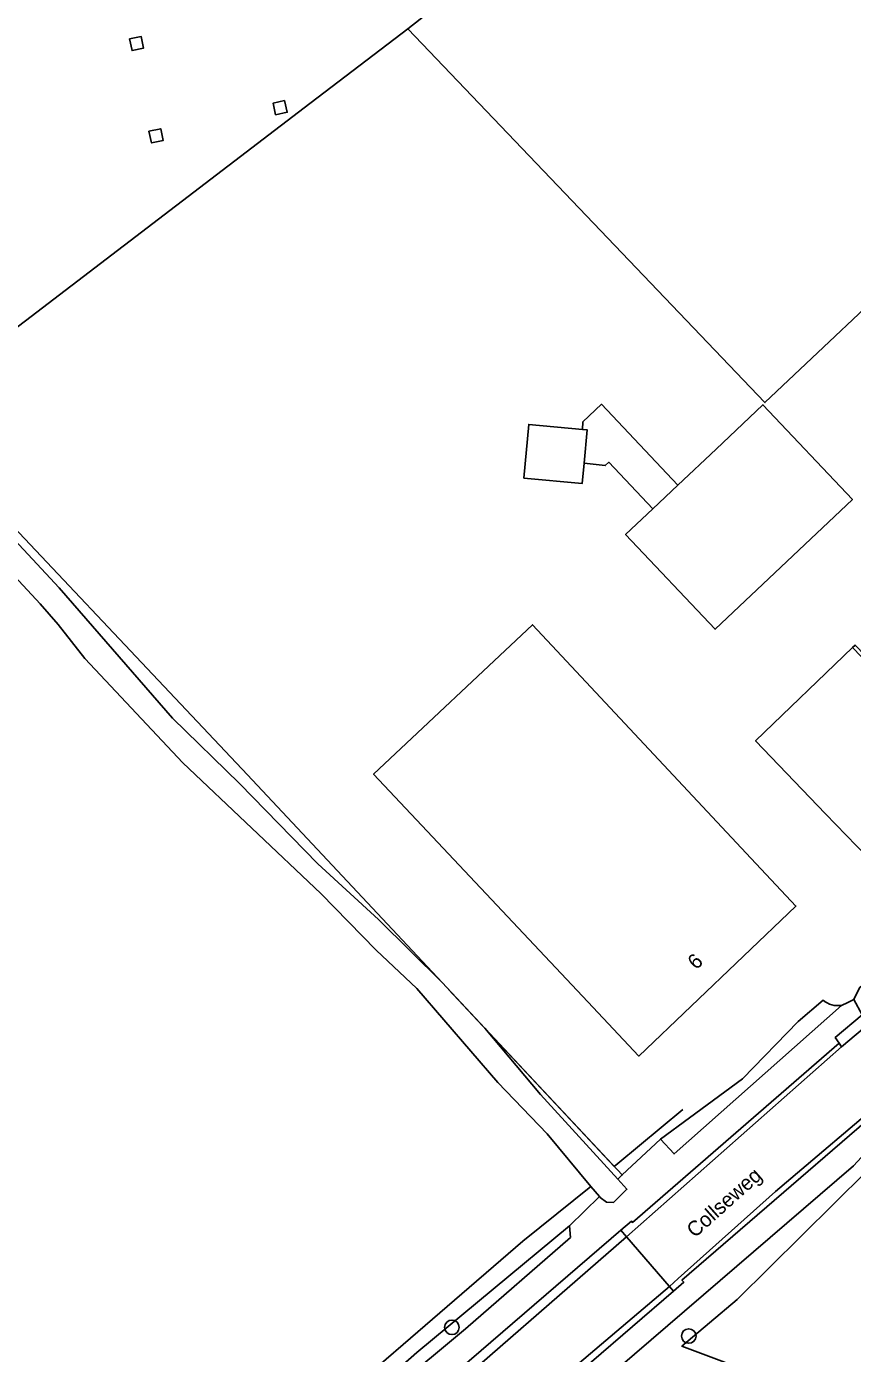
# Model space of a CAD drawing. Extents: x 164494 to 166241, y 382475 to 384495.
# Drawn here: x 165298.9 to 165354.5, y 384025.1 to 384114.4 of the extents above; entities that cross this region are included whole.
import ezdxf

# ---------------------------------------------------------------- set-up
doc = ezdxf.new("R2010")
doc.units = 0
for name, color, linetype in [('IMGEO_Berm_halfverhard', 7, 'Continuous'), ('IMGEO_Berm_open', 7, 'Continuous'), ('IMGEO_Boom', 7, 'Continuous'), ('IMGEO_Erf', 7, 'Continuous'), ('IMGEO_Grasland_agrarisch', 7, 'Continuous'), ('IMGEO_Grasland_overig', 7, 'Continuous'), ('IMGEO_Groenvoorziening', 7, 'Continuous'), ('IMGEO_Hek', 7, 'Continuous'), ('IMGEO_Hoogspanningsmast', 7, 'Continuous'), ('IMGEO_Openbare_ruimte_label', 7, 'Continuous'), ('IMGEO_Pand', 7, 'Continuous'), ('IMGEO_Pand_nummerreeks', 7, 'Continuous'), ('IMGEO_Rijbaan_lokaal_gesloten', 7, 'Continuous'), ('IMGEO_Waterloop', 7, 'Continuous')]:
    doc.layers.add(name, color=color, linetype=linetype)

msp = doc.modelspace()

# ---------------------------------------------------------------- linework, layer by layer
at = {"layer": 'IMGEO_Berm_halfverhard'}
msp.add_lwpolyline([(165398.089, 384073.33), (165398.624, 384073.651), (165398.403, 384074.002), (165394.851, 384071.884), (165389.473, 384068.311), (165384.606, 384064.9), (165379.087, 384060.555), (165368.742, 384052.317), (165357.153, 384042.664), (165349.337, 384036.022), (165342.774, 384030.162), (165342.196, 384029.629), (165342.457, 384029.327), (165343.149, 384029.924), (165343.032, 384030.052), (165361.191, 384045.73)], dxfattribs=at)
for points in [[(165353.778, 384045.772), (165353.618, 384046.006), (165339.695, 384033.942), (165339.626, 384034.037), (165338.914, 384033.424), (165339.3, 384032.977)], [(165339.3, 384032.977), (165338.914, 384033.424), (165325.135, 384021.562), (165325.577, 384021.044)], [(165342.457, 384029.327), (165342.196, 384029.629), (165342.192, 384029.633), (165328.3, 384017.851), (165328.304, 384017.847), (165328.664, 384017.425)]]:
    msp.add_lwpolyline(points, close=True, dxfattribs=at)
at = {"layer": 'IMGEO_Berm_open'}
msp.add_lwpolyline([(165380.141, 384067.277), (165379.794, 384067.601), (165367.867, 384058.185), (165366.467, 384057.026), (165355.319, 384047.804), (165355.158, 384047.926), (165353.349, 384046.386), (165353.618, 384046.006), (165353.778, 384045.772), (165361.803, 384052.529)], close=True, dxfattribs=at)
at = {"layer": 'IMGEO_Boom'}
for centre in [(165327.543, 384026.884), (165343.493, 384026.298)]:
    msp.add_circle(centre, 0.489, dxfattribs=at)
at = {"layer": 'IMGEO_Erf'}
for points in [[(165391.678, 384085.733), (165388.411, 384089.95), (165382.449, 384096.307), (165369.932, 384109.251), (165348.615, 384089.13), (165324.577, 384114.294), (165317.6, 384108.966), (165252.153, 384058.979), (165253.127, 384057.056), (165268.295, 384067.905), (165290.735, 384085.47), (165292.37, 384086.749), (165313.785, 384064.085), (165326.891, 384050.086), (165329.75, 384047.033), (165339.009, 384037.144), (165341.59, 384039.543), (165343.541, 384040.983), (165347.115, 384043.622), (165350.846, 384047.468), (165352.53, 384048.91)], [(165353.783, 384048.557), (165354.194, 384048.759), (165354.605, 384048.96), (165354.993, 384049.748), (165365.174, 384058.493), (165365.22, 384058.534), (165379.994, 384071.652)]]:
    msp.add_lwpolyline(points, dxfattribs=at)
for points in [[(165354.508, 384082.604), (165345.259, 384073.877), (165339.236, 384080.26), (165341.068, 384081.988), (165338.113, 384085.12), (165337.868, 384084.889), (165336.438, 384085.049), (165336.314, 384083.697), (165332.389, 384084.057), (165332.72, 384087.663), (165336.344, 384087.331), (165336.359, 384087.849), (165337.606, 384089.026), (165342.75, 384083.575), (165345.33, 384086.01), (165348.485, 384088.987)], [(165370.222, 384071.391), (165367.373, 384068.646), (165362.702, 384064.146), (165361.201, 384062.699), (165356.175, 384057.856), (165352.706, 384061.457), (165347.988, 384066.354), (165354.518, 384072.645), (165354.686, 384072.807), (165356.732, 384070.685), (165361.259, 384075.024), (165361.593, 384075.344), (165361.693, 384075.439), (165359.686, 384077.533), (165370.419, 384087.822), (165372.426, 384085.728), (165378.512, 384079.379)], [(165347.349, 384058.806), (165350.703, 384055.242), (165340.124, 384045.146), (165336.698, 384048.787), (165322.274, 384064.121), (165332.965, 384074.179)]]:
    msp.add_lwpolyline(points, close=True, dxfattribs=at)
msp.add_arc((165353.536, 384050.08), 1.543, 229.31259, 279.21982, dxfattribs=at)
at = {"layer": 'IMGEO_Grasland_agrarisch'}
for points in [[(165252.135, 384126.212), (165259.359, 384109.977), (165260.629, 384106.524), (165261.006, 384104.035), (165260.836, 384103.097), (165257.621, 384100.164), (165254.64, 384097.443), (165239.617, 384083.733), (165252.153, 384058.979), (165317.6, 384108.966), (165324.577, 384114.294), (165325.92, 384115.348)], [(165315.061, 384017.793), (165332.31, 384032.682), (165336.908, 384036.367), (165333.948, 384039.91), (165330.625, 384043.365), (165325.183, 384049.687), (165322.446, 384052.267), (165318.721, 384056.08), (165309.424, 384064.873), (165302.838, 384071.905), (165301.022, 384074.192), (165299.817, 384075.596), (165291.463, 384084.552), (165291.38, 384084.656), (165290.735, 384085.47), (165268.295, 384067.905), (165253.127, 384057.056), (165251.113, 384052.179), (165251.197, 384048.404), (165254.594, 384042.784), (165256.355, 384037.961), (165258.159, 384032.215), (165259.249, 384027.161), (165259.336, 384024.7)]]:
    msp.add_lwpolyline(points, dxfattribs=at)
for points in [[(165305.838, 384113.61), (165306.621, 384113.776), (165306.787, 384112.993), (165306.004, 384112.827)], [(165316.278, 384109.459), (165316.454, 384108.678), (165315.671, 384108.512), (165315.498, 384109.282)], [(165307.145, 384107.396), (165307.938, 384107.564), (165308.104, 384106.782), (165307.321, 384106.616)]]:
    msp.add_lwpolyline(points, close=True, dxfattribs=at)
at = {"layer": 'IMGEO_Grasland_overig'}
for points in [[(165292.678, 384085.685), (165301.093, 384076.655), (165308.723, 384067.888), (165313.252, 384063.5), (165318.507, 384058.078), (165322.591, 384054.348), (165326.891, 384050.086), (165313.785, 384064.085), (165292.37, 384086.749)], [(165337.481, 384035.681), (165336.908, 384036.367), (165332.31, 384032.682), (165315.061, 384017.793)], [(165285.244, 383989.372), (165286.771, 383991.023), (165305.148, 384007.51), (165310.172, 384012.285), (165316.571, 384017.609), (165325.174, 384025.19), (165335.45, 384033.721), (165337.481, 384035.681)]]:
    msp.add_lwpolyline(points, dxfattribs=at)
at = {"layer": 'IMGEO_Groenvoorziening'}
for points in [[(165356.604, 384122.555), (165348.288, 384131.158), (165347.388, 384132.202), (165325.92, 384115.348), (165324.577, 384114.294), (165348.615, 384089.13), (165369.932, 384109.251), (165369.504, 384109.693), (165363.145, 384115.787)], [(165329.75, 384047.033), (165333.509, 384042.566), (165338.707, 384036.864), (165339.009, 384037.144)]]:
    msp.add_lwpolyline(points, close=True, dxfattribs=at)
for points in [[(165380.105, 384059.954), (165378.251, 384059.429), (165361.191, 384045.73), (165343.032, 384030.052), (165343.149, 384029.924), (165342.457, 384029.327), (165328.664, 384017.425), (165327.921, 384016.784), (165327.858, 384016.829), (165300.992, 383993.615)], [(165333.093, 384019.286), (165354.573, 384037.755), (165355.922, 384039.225), (165365.795, 384048.014), (165371.241, 384052.452), (165380.109, 384059.294), (165381.762, 384060.186), (165382.283, 384060.069), (165382.106, 384059.628), (165381.07, 384059.101), (165379.062, 384057.607), (165374.751, 384053.736), (165362.707, 384043.753), (165359.803, 384041.672), (165346.76, 384028.762), (165343.024, 384025.615), (165348.876, 384023.417)], [(165325.135, 384021.562), (165338.914, 384033.424), (165339.626, 384034.037), (165339.695, 384033.942), (165353.618, 384046.006), (165353.349, 384046.386), (165355.158, 384047.926), (165354.605, 384048.96), (165354.194, 384048.759), (165353.783, 384048.557), (165342.506, 384038.557), (165341.59, 384039.543), (165339.009, 384037.144), (165338.707, 384036.864), (165339.33, 384036.181), (165338.418, 384035.282), (165337.958, 384035.319), (165337.536, 384035.616), (165337.481, 384035.681), (165335.45, 384033.721), (165335.536, 384032.942), (165328.461, 384026.792), (165318.663, 384018.644)]]:
    msp.add_lwpolyline(points, dxfattribs=at)
at = {"layer": 'IMGEO_Hek'}
for points in [[(165253.127, 384057.056), (165268.295, 384067.905), (165292.37, 384086.749), (165313.785, 384064.085), (165326.891, 384050.086)], [(165338.713, 384037.924), (165338.468, 384037.722), (165327.318, 384049.631)], [(165343.084, 384041.54), (165338.713, 384037.924)]]:
    msp.add_lwpolyline(points, dxfattribs=at)
at = {"layer": 'IMGEO_Hoogspanningsmast'}
for points in [[(165305.838, 384113.61), (165306.004, 384112.827), (165306.787, 384112.993), (165306.621, 384113.776)], [(165316.278, 384109.459), (165315.498, 384109.282), (165315.671, 384108.512), (165316.454, 384108.678)], [(165307.145, 384107.396), (165307.321, 384106.616), (165308.104, 384106.782), (165307.938, 384107.564)]]:
    msp.add_lwpolyline(points, close=True, dxfattribs=at)
at = {"layer": 'IMGEO_Pand'}
for points in [[(165337.606, 384089.026), (165336.359, 384087.849), (165336.344, 384087.331), (165336.645, 384087.303), (165336.438, 384085.049), (165337.868, 384084.889), (165338.113, 384085.12), (165341.068, 384081.988), (165342.75, 384083.575)], [(165342.75, 384083.575), (165341.068, 384081.988), (165339.236, 384080.26), (165345.259, 384073.877), (165354.508, 384082.604), (165348.485, 384088.987), (165345.33, 384086.01)], [(165336.344, 384087.331), (165332.72, 384087.663), (165332.389, 384084.057), (165336.314, 384083.697), (165336.438, 384085.049), (165336.645, 384087.303)], [(165332.965, 384074.179), (165322.274, 384064.121), (165336.698, 384048.787), (165340.124, 384045.146), (165350.703, 384055.242), (165347.349, 384058.806)], [(165362.702, 384064.146), (165354.518, 384072.645), (165347.988, 384066.354), (165352.706, 384061.457), (165356.175, 384057.856), (165361.201, 384062.699)]]:
    msp.add_lwpolyline(points, close=True, dxfattribs=at)
at = {"layer": 'IMGEO_Rijbaan_lokaal_gesloten'}
msp.add_lwpolyline([(165391.605, 384076.232), (165387.482, 384072.953), (165380.854, 384067.745), (165380.141, 384067.277), (165361.803, 384052.529), (165353.778, 384045.772), (165339.3, 384032.977), (165339.311, 384032.965), (165342.18, 384029.647), (165342.192, 384029.633), (165342.196, 384029.629), (165342.774, 384030.162), (165349.337, 384036.022), (165357.153, 384042.664), (165368.742, 384052.317), (165379.087, 384060.555), (165384.606, 384064.9), (165389.473, 384068.311), (165394.851, 384071.884), (165398.403, 384074.002)], dxfattribs=at)
msp.add_lwpolyline([(165342.192, 384029.633), (165342.18, 384029.647), (165339.311, 384032.965), (165339.3, 384032.977), (165325.577, 384021.044), (165328.3, 384017.851)], close=True, dxfattribs=at)
at = {"layer": 'IMGEO_Waterloop'}
for points in [[(165329.75, 384047.033), (165326.891, 384050.086), (165322.591, 384054.348), (165318.507, 384058.078), (165313.252, 384063.5), (165308.723, 384067.888), (165301.093, 384076.655), (165292.678, 384085.685)], [(165291.38, 384084.656), (165291.463, 384084.552), (165299.817, 384075.596), (165301.022, 384074.192), (165302.838, 384071.905), (165309.424, 384064.873), (165318.721, 384056.08), (165322.446, 384052.267), (165325.183, 384049.687), (165330.625, 384043.365), (165333.948, 384039.91), (165336.908, 384036.367), (165337.481, 384035.681), (165337.536, 384035.616), (165337.958, 384035.319), (165338.418, 384035.282), (165339.33, 384036.181), (165338.707, 384036.864), (165333.509, 384042.566), (165329.75, 384047.033)], [(165348.876, 384023.417), (165343.024, 384025.615), (165346.76, 384028.762), (165359.803, 384041.672), (165362.707, 384043.753), (165374.751, 384053.736), (165379.062, 384057.607), (165381.07, 384059.101), (165382.106, 384059.628), (165382.283, 384060.069), (165381.762, 384060.186), (165380.109, 384059.294), (165371.241, 384052.452), (165365.795, 384048.014), (165355.922, 384039.225), (165354.573, 384037.755), (165333.093, 384019.286)], [(165352.53, 384048.91), (165350.846, 384047.468), (165347.115, 384043.622), (165343.541, 384040.983), (165341.59, 384039.543), (165342.506, 384038.557), (165353.783, 384048.557)], [(165282.52, 383986.145), (165283.547, 383986.655), (165284.63, 383987.46), (165285.87, 383988.632), (165292.307, 383994.716), (165294.231, 383996.254), (165306.385, 384007.779), (165318.663, 384018.644), (165328.461, 384026.792), (165335.536, 384032.942), (165335.45, 384033.721), (165325.174, 384025.19), (165316.571, 384017.609), (165310.172, 384012.285), (165305.148, 384007.51), (165286.771, 383991.023), (165285.244, 383989.372)]]:
    msp.add_lwpolyline(points, dxfattribs=at)
msp.add_arc((165353.536, 384050.08), 1.543, 229.31259, 279.21982, dxfattribs=at)

# ---------------------------------------------------------------- texts
at = {"layer": 'IMGEO_Openbare_ruimte_label'}
msp.add_text('Collseweg', height=1, rotation=41.75725, dxfattribs=at).set_placement((165343.896, 384032.865))
at = {"layer": 'IMGEO_Pand_nummerreeks'}
msp.add_text('6', height=1, rotation=43.65938, dxfattribs=at).set_placement((165343.991, 384050.91))

doc.saveas('drawing.dxf')
